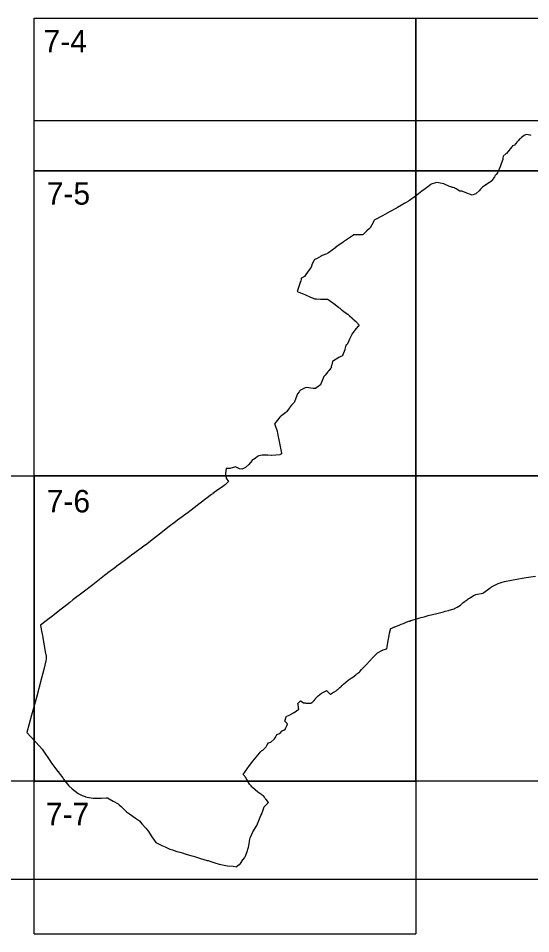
# Model space of a CAD drawing. Extents: x -449577 to -425530, y -1150048 to -1121091.
# Drawn here: x -436768.8 to -436559.1, y -1126653.4 to -1126278.4 of the extents above; entities that cross this region are included whole.
import ezdxf

# ---------------------------------------------------------------- set-up
doc = ezdxf.new("R2010")
doc.units = 0
for name, color, linetype in [('Vrstva 1', 7, 'Continuous'), ('Vrstva 10', 7, 'Continuous'), ('Vrstva 4', 7, 'Continuous')]:
    doc.layers.add(name, color=color, linetype=linetype)

msp = doc.modelspace()

# ---------------------------------------------------------------- linework, layer by layer
at = {"layer": 'Vrstva 1'}
for points in [[(-436558.93, -1126326.41), (-436559.39, -1126326.32), (-436560.98, -1126326), (-436561.28, -1126326.11), (-436561.84, -1126326.46), (-436562.39, -1126326.78), (-436562.88, -1126327.24), (-436563.41, -1126327.73), (-436563.81, -1126328.12), (-436563.82, -1126328.13), (-436564.15, -1126328.47), (-436564.28, -1126328.61), (-436564.79, -1126329.16), (-436565.24, -1126329.71), (-436565.4, -1126329.9), (-436565.76, -1126330.33), (-436566.5, -1126330.66), (-436566.52, -1126330.66), (-436566.72, -1126330.91), (-436567.58, -1126331.93), (-436567.96, -1126332.38), (-436569.09, -1126333.74), (-436569.1, -1126333.75), (-436570.34, -1126334.92), (-436570.46, -1126335.76), (-436570.51, -1126336.13), (-436570.55, -1126336.23), (-436571.03, -1126337.58), (-436571.47, -1126338.82), (-436571.5, -1126338.9), (-436571.8, -1126339.59), (-436572.73, -1126341.77), (-436572.75, -1126341.78), (-436573.32, -1126342.46), (-436573.62, -1126342.81), (-436573.62, -1126342.82), (-436573.96, -1126343.36), (-436574.83, -1126344.75), (-436574.92, -1126344.89), (-436575.09, -1126345.02), (-436575.62, -1126345.41), (-436576.23, -1126345.86), (-436576.23, -1126345.86), (-436577.2, -1126346.49), (-436577.33, -1126346.58), (-436577.51, -1126346.7), (-436578.81, -1126347.56), (-436578.82, -1126347.57), (-436579.08, -1126347.83), (-436579.2, -1126347.95), (-436579.42, -1126348.18), (-436579.7, -1126348.46), (-436580.27, -1126349.03), (-436581.43, -1126350.19), (-436581.63, -1126350.27), (-436583.13, -1126350.84), (-436585.94, -1126349.72), (-436585.94, -1126349.73), (-436585.95, -1126349.75), (-436586.86, -1126349.37), (-436587.17, -1126349.24), (-436587.19, -1126349.24), (-436587.58, -1126349.24), (-436588.06, -1126349.24), (-436589.62, -1126348.25), (-436589.88, -1126348.12), (-436590.17, -1126347.96), (-436590.23, -1126347.93), (-436590.27, -1126347.91), (-436590.81, -1126347.68), (-436590.86, -1126347.68), (-436590.87, -1126347.68), (-436591.02, -1126347.67), (-436591.14, -1126347.66), (-436591.45, -1126347.64), (-436591.47, -1126347.64), (-436591.47, -1126347.64), (-436591.58, -1126347.6), (-436591.82, -1126347.5), (-436592.42, -1126347.25), (-436592.58, -1126347.18), (-436594.1, -1126346.45), (-436594.72, -1126346.27), (-436595.39, -1126346.07), (-436597.71, -1126345.64), (-436597.72, -1126345.64), (-436598.12, -1126345.75), (-436599.86, -1126346.33), (-436599.99, -1126346.44), (-436601.2, -1126347.4), (-436601.2, -1126347.4), (-436602.35, -1126348.27), (-436602.92, -1126348.7), (-436603.5, -1126349.14), (-436603.66, -1126349.26), (-436605.79, -1126350.9), (-436606.86, -1126351.72), (-436607.33, -1126352.06), (-436608.09, -1126352.57), (-436608.34, -1126352.73), (-436608.93, -1126353.12), (-436608.97, -1126353.15), (-436609.18, -1126353.29), (-436610.09, -1126353.89), (-436610.1, -1126353.89), (-436610.57, -1126354.15), (-436610.72, -1126354.23), (-436610.9, -1126354.33), (-436611.36, -1126354.58), (-436611.54, -1126354.69), (-436611.7, -1126354.78), (-436611.8, -1126354.84), (-436612.04, -1126354.98), (-436613.7, -1126355.92), (-436613.87, -1126356.01), (-436614.1, -1126356.14), (-436616.57, -1126357.54), (-436616.69, -1126357.61), (-436618.8, -1126358.74), (-436619.82, -1126359.29), (-436623.16, -1126361.1), (-436623.33, -1126361.4), (-436623.39, -1126361.51), (-436624.17, -1126362.97), (-436624.85, -1126364.29), (-436624.99, -1126364.42), (-436625.08, -1126364.5), (-436626.22, -1126365.54), (-436627.73, -1126366.92), (-436627.9, -1126367.07), (-436627.9, -1126367.08), (-436628.37, -1126367.09), (-436631.56, -1126367.18), (-436631.57, -1126367.18), (-436632, -1126367.47), (-436632.83, -1126368.04), (-436635.3, -1126369.7), (-436635.34, -1126369.72), (-436635.58, -1126369.9), (-436635.85, -1126370.1), (-436638.83, -1126372.23), (-436638.9, -1126372.28), (-436641.9, -1126374.46), (-436642.37, -1126374.8), (-436642.53, -1126374.86), (-436644.47, -1126375.58), (-436644.48, -1126375.58), (-436644.87, -1126375.82), (-436646.75, -1126376.98), (-436647.67, -1126377.19), (-436647.92, -1126377.7), (-436648.68, -1126379.21), (-436648.69, -1126379.22), (-436648.76, -1126379.48), (-436648.96, -1126380.32), (-436649.79, -1126381.43), (-436651.16, -1126383.38), (-436651.72, -1126384.19), (-436651.75, -1126384.21), (-436652.91, -1126384.85), (-436653.01, -1126384.91), (-436653.08, -1126385.3), (-436653.23, -1126386.11), (-436653.28, -1126386.3), (-436654.57, -1126389.88), (-436654.74, -1126390.36), (-436654.71, -1126390.35), (-436654.69, -1126390.34), (-436654.01, -1126390.6), (-436652.2, -1126391.26), (-436651.58, -1126391.55), (-436649.29, -1126392.63), (-436649.27, -1126392.63), (-436648.11, -1126393.1), (-436647.64, -1126393.28), (-436647.61, -1126393.29), (-436647.18, -1126393.32), (-436647.04, -1126393.33), (-436646.82, -1126393.35), (-436645.22, -1126393.45), (-436644.18, -1126393.52), (-436643.13, -1126393.49), (-436642.29, -1126393.46), (-436642.28, -1126393.46), (-436642, -1126393.61), (-436641.63, -1126393.87), (-436641.08, -1126394.25), (-436640.69, -1126394.53), (-436639.13, -1126395.67), (-436638.96, -1126395.79), (-436637.85, -1126396.71), (-436637.46, -1126397.03), (-436637.28, -1126397.18), (-436636.53, -1126397.79), (-436636.26, -1126398.02), (-436635.66, -1126398.51), (-436635.44, -1126398.69), (-436634.8, -1126399.11), (-436634.05, -1126399.61), (-436634.02, -1126399.63), (-436633.26, -1126400.31), (-436632.38, -1126401.09), (-436631.94, -1126401.47), (-436630.93, -1126402.36), (-436630.67, -1126402.59), (-436630.62, -1126402.64), (-436630.52, -1126402.74), (-436630.51, -1126402.75), (-436630.42, -1126402.85), (-436630.39, -1126402.88), (-436629.34, -1126404.11), (-436629.35, -1126404.12), (-436629.79, -1126404.61), (-436629.85, -1126404.68), (-436630.42, -1126405.31), (-436631.24, -1126406.37), (-436631.41, -1126406.58), (-436631.97, -1126407.3), (-436632.27, -1126407.83), (-436632.29, -1126407.87), (-436632.3, -1126407.89), (-436632.43, -1126408.17), (-436633.23, -1126409.84), (-436633.54, -1126410.48), (-436634.16, -1126411.77), (-436634.27, -1126412.01), (-436634.28, -1126412.01), (-436634.32, -1126412.04), (-436634.61, -1126412.24), (-436634.69, -1126412.28), (-436634.74, -1126412.38), (-436634.83, -1126412.58), (-436634.92, -1126412.86), (-436635.09, -1126413.42), (-436635.1, -1126413.44), (-436635.22, -1126413.94), (-436635.24, -1126414.01), (-436635.23, -1126414.07), (-436635.22, -1126414.15), (-436635.22, -1126414.22), (-436635.23, -1126414.27), (-436636.11, -1126416.6), (-436636.13, -1126416.65), (-436636.15, -1126416.69), (-436636.16, -1126416.7), (-436636.86, -1126417), (-436637.11, -1126417.11), (-436637.58, -1126417.35), (-436640.19, -1126419.04), (-436640.19, -1126419.04), (-436640.56, -1126420.35), (-436640.64, -1126420.61), (-436640.75, -1126421.03), (-436640.81, -1126421.24), (-436640.81, -1126421.25), (-436640.8, -1126421.25), (-436640.63, -1126421.41), (-436640.64, -1126421.42), (-436641, -1126421.81), (-436641.8, -1126422.81), (-436641.81, -1126422.82), (-436642.02, -1126423.07), (-436642.02, -1126423.08), (-436642.14, -1126423.23), (-436643.3, -1126424.58), (-436643.84, -1126425.21), (-436644.6, -1126427.16), (-436644.98, -1126428.18), (-436645.11, -1126428.53), (-436646.64, -1126429.63), (-436647.26, -1126430.07), (-436647.44, -1126430.11), (-436647.46, -1126430.11), (-436648.09, -1126430.02), (-436650.93, -1126429.6), (-436651.42, -1126429.84), (-436652.75, -1126430.48), (-436653.29, -1126430.74), (-436653.32, -1126430.77), (-436653.75, -1126431.18), (-436653.92, -1126431.4), (-436654.58, -1126432.25), (-436654.58, -1126432.26), (-436655.25, -1126434.06), (-436655.82, -1126435.56), (-436655.82, -1126435.56), (-436655.96, -1126435.78), (-436656.29, -1126436.15), (-436657.01, -1126436.95), (-436657.71, -1126437.72), (-436657.72, -1126437.74), (-436657.85, -1126437.93), (-436658.92, -1126439.5), (-436659.39, -1126439.88), (-436660.96, -1126441.14), (-436661.63, -1126441.68), (-436661.73, -1126441.76), (-436661.76, -1126441.8), (-436662.88, -1126443.23), (-436664.02, -1126444.54), (-436663.87, -1126444.71), (-436663.86, -1126444.74), (-436663.86, -1126444.75), (-436662.85, -1126447.51), (-436662.57, -1126449.17), (-436662.25, -1126451.12), (-436661.84, -1126453.08), (-436661.11, -1126456.58), (-436661.07, -1126456.78), (-436661.72, -1126457.12), (-436661.84, -1126457.19), (-436665.01, -1126457.45), (-436665.17, -1126457.45), (-436666.66, -1126457.42), (-436669.05, -1126457.4), (-436670.33, -1126457.67), (-436670.93, -1126457.94), (-436671.91, -1126458.74), (-436673.21, -1126459.61), (-436673.3, -1126459.72), (-436674.46, -1126461.14), (-436675.91, -1126462.48), (-436676.6, -1126462.8), (-436677.2, -1126463.08), (-436678.37, -1126463.01), (-436679.98, -1126462.16), (-436682.22, -1126462.83), (-436683.7, -1126462.8), (-436684.08, -1126464.91), (-436684.09, -1126464.93), (-436684.1, -1126465.02), (-436683.81, -1126466.83), (-436682.84, -1126468.15), (-436682.83, -1126468.17), (-436683.57, -1126468.92), (-436684.18, -1126469.48), (-436684.43, -1126469.71), (-436685.23, -1126470.34), (-436687.16, -1126471.57), (-436687.22, -1126471.61), (-436689.19, -1126473.14), (-436689.25, -1126473.18), (-436689.74, -1126473.56), (-436694.4, -1126477.02), (-436694.43, -1126477.05), (-436699.38, -1126480.81), (-436703.64, -1126484.06), (-436704.52, -1126484.72), (-436707.09, -1126486.66), (-436711.09, -1126489.79), (-436713.53, -1126491.66), (-436716.84, -1126494.19), (-436716.89, -1126494.23), (-436721.68, -1126497.74), (-436721.91, -1126497.92), (-436725.52, -1126500.6), (-436727.91, -1126502.42), (-436729.88, -1126503.9), (-436732.2, -1126505.65), (-436732.43, -1126505.82), (-436733.56, -1126506.71), (-436738.38, -1126510.51), (-436742.27, -1126513.46), (-436746.49, -1126516.71), (-436747.78, -1126517.71), (-436750.17, -1126519.59), (-436751.35, -1126520.51), (-436755.29, -1126523.56), (-436756.22, -1126524.27), (-436757.46, -1126525.23), (-436759.78, -1126527.03), (-436759.78, -1126527.03), (-436759.74, -1126527.21), (-436759.45, -1126528.59), (-436759.42, -1126528.75), (-436758.89, -1126531.29), (-436758.73, -1126532.02), (-436758.73, -1126532.06), (-436757.8, -1126537.94), (-436757.79, -1126537.97), (-436757.49, -1126539.7), (-436757.49, -1126539.72), (-436757.43, -1126540.09), (-436757.37, -1126540.51), (-436757.4, -1126540.88), (-436757.55, -1126541.61), (-436757.93, -1126543.4), (-436758.22, -1126544.58), (-436758.24, -1126544.63), (-436759.35, -1126548.8), (-436761.45, -1126556.68), (-436763.44, -1126563.9), (-436765.37, -1126571), (-436765.38, -1126571.04), (-436760.1, -1126576.64), (-436759.05, -1126577.77), (-436758.29, -1126578.99), (-436756.27, -1126582.05), (-436756.22, -1126582.12), (-436755.21, -1126583.53), (-436755.05, -1126583.74), (-436753.17, -1126586.22), (-436752.6, -1126586.96), (-436752.57, -1126587), (-436752.05, -1126587.72), (-436750.67, -1126589.62), (-436750.34, -1126590.07), (-436748.19, -1126592.79), (-436746.79, -1126594.01), (-436744.39, -1126595.99), (-436742.65, -1126596.74), (-436741.46, -1126597.26), (-436741.33, -1126597.31), (-436740, -1126597.59), (-436739.86, -1126597.62), (-436738.24, -1126597.95), (-436738.21, -1126597.95), (-436737.25, -1126597.93), (-436736.87, -1126597.93), (-436736.35, -1126597.92), (-436735.67, -1126597.91), (-436734.76, -1126597.87), (-436732.81, -1126597.71), (-436732.36, -1126597.78), (-436731.7, -1126598.13), (-436729.98, -1126599.08), (-436728.02, -1126600.18), (-436727.5, -1126600.66), (-436726.78, -1126601.34), (-436725.98, -1126602.09), (-436724.66, -1126603.39), (-436724.52, -1126603.49), (-436723.33, -1126604.34), (-436720.92, -1126606.05), (-436719.28, -1126607.23), (-436718.23, -1126608.41), (-436716.59, -1126610.23), (-436715.95, -1126610.94), (-436715.59, -1126611.53), (-436715.13, -1126612.27), (-436714.19, -1126613.74), (-436713.56, -1126614.66), (-436712.52, -1126616.1), (-436711.45, -1126616.61), (-436710.07, -1126617.26), (-436708.76, -1126617.87), (-436706.79, -1126618.76), (-436705.66, -1126619.11), (-436703.94, -1126619.68), (-436703.79, -1126619.73), (-436702.7, -1126620.05), (-436701.28, -1126620.47), (-436701.27, -1126620.47), (-436701.06, -1126620.53), (-436701, -1126620.55), (-436700.14, -1126620.81), (-436697.75, -1126621.5), (-436697.63, -1126621.54), (-436697.15, -1126621.68), (-436694.22, -1126622.55), (-436691.53, -1126623.38), (-436691.19, -1126623.48), (-436690.43, -1126623.71), (-436688.42, -1126624.33), (-436686.69, -1126624.88), (-436683.23, -1126625.62)], [(-436683.23, -1126625.62), (-436680.84, -1126625.81), (-436679.64, -1126626.04), (-436679.53, -1126625.95), (-436677.95, -1126624.68), (-436676.92, -1126623.2), (-436676.81, -1126623.05), (-436676.29, -1126622.29), (-436676.18, -1126622.12), (-436676.04, -1126621.89), (-436675.66, -1126621.26), (-436675.39, -1126620.43), (-436675.37, -1126620.36), (-436675.35, -1126620.31), (-436675.32, -1126620.2), (-436675.29, -1126620.11), (-436675.29, -1126620.1), (-436674.66, -1126617.9), (-436674.52, -1126617.38), (-436674.07, -1126614.63), (-436674.07, -1126614.63), (-436673.88, -1126614.19), (-436673.62, -1126613.57), (-436672.83, -1126611.74), (-436671.26, -1126609.09), (-436669.51, -1126604.96), (-436669.19, -1126604.32), (-436669.15, -1126604.19), (-436668.76, -1126603.09), (-436668.17, -1126601.42), (-436666.49, -1126599.71), (-436667.42, -1126598.47), (-436667.48, -1126598.38), (-436667.53, -1126598.32), (-436667.56, -1126598.28), (-436667.63, -1126598.18), (-436667.68, -1126598.1), (-436667.76, -1126597.98), (-436668.12, -1126597.46), (-436668.49, -1126597), (-436669.06, -1126596.63), (-436669.16, -1126596.57), (-436670.81, -1126595.5), (-436673, -1126593.56), (-436673.13, -1126593.39), (-436673.16, -1126593.35), (-436673.24, -1126593.25), (-436673.58, -1126592.83), (-436673.91, -1126592.42), (-436674.17, -1126592.1), (-436674.65, -1126591.51), (-436674.73, -1126591.41), (-436675.23, -1126590.45), (-436675.52, -1126589.89), (-436675.75, -1126589.46), (-436675.8, -1126589.37), (-436675.84, -1126589.32), (-436676.1, -1126589.03), (-436676.3, -1126588.8), (-436676.56, -1126588.51), (-436676.78, -1126588.26), (-436674.92, -1126585.52), (-436674.83, -1126585.4), (-436674.51, -1126584.95), (-436674.19, -1126584.51), (-436672.86, -1126582.68), (-436670.18, -1126579.42), (-436669.83, -1126579.1), (-436669.12, -1126578.4), (-436669.01, -1126578.31), (-436668.82, -1126578.17), (-436668.22, -1126577.69), (-436667.36, -1126576.85), (-436666.95, -1126576.09), (-436666.48, -1126575.22), (-436665.43, -1126574.98), (-436664.03, -1126573.55), (-436663.49, -1126572.7), (-436663.48, -1126572.69), (-436663.48, -1126572.67), (-436663.27, -1126572.34), (-436663.22, -1126572.26), (-436662.98, -1126571.87), (-436661.82, -1126571.43), (-436660.8, -1126570.25), (-436660.27, -1126570.05), (-436660.15, -1126570), (-436659.73, -1126569.84), (-436659.51, -1126569.45), (-436659.46, -1126569.36), (-436659.29, -1126569.06), (-436658.88, -1126568.32), (-436658.68, -1126567.41), (-436658.68, -1126567.39), (-436658.67, -1126567.38), (-436659.72, -1126566.39), (-436659.74, -1126566.38), (-436659.75, -1126566.36), (-436659.8, -1126566.32), (-436659.15, -1126564.52), (-436659.08, -1126564.32), (-436658.92, -1126564.26), (-436658.19, -1126563.97), (-436657.5, -1126563.7), (-436657.38, -1126563.65), (-436656.17, -1126562.94), (-436656.05, -1126562.86), (-436656.05, -1126562.86), (-436656.04, -1126562.85), (-436655.92, -1126562.78), (-436654.06, -1126561.38), (-436654.06, -1126561.34), (-436654.09, -1126561.18), (-436654.16, -1126560.7), (-436654.22, -1126560.35), (-436654.32, -1126559.73), (-436654.34, -1126559.62), (-436654.36, -1126559.49), (-436654.38, -1126559.32), (-436654.41, -1126559.18), (-436653.87, -1126558.62), (-436653.31, -1126558.05), (-436653.27, -1126558), (-436653.13, -1126558.1), (-436652.13, -1126558.89), (-436651.45, -1126558.9), (-436651.39, -1126558.9), (-436651.14, -1126558.91), (-436650.98, -1126558.91), (-436649.67, -1126558.93), (-436649.04, -1126558.95), (-436648.77, -1126558.79), (-436648.74, -1126558.77), (-436648.62, -1126558.7), (-436648.48, -1126558.61), (-436648.44, -1126558.58), (-436647.9, -1126557.98), (-436647.79, -1126557.86), (-436647.7, -1126557.76), (-436647.53, -1126557.58), (-436647.45, -1126557.49), (-436647.34, -1126557.37), (-436647.31, -1126557.33), (-436647.28, -1126557.3), (-436647.23, -1126557.24), (-436647.14, -1126557.13), (-436646.74, -1126556.63), (-436646.53, -1126556.37), (-436646.28, -1126556.05), (-436646.17, -1126555.97), (-436644.71, -1126554.9), (-436644.5, -1126554.77), (-436643.14, -1126554), (-436642.74, -1126553.77), (-436642.74, -1126553.77), (-436642.6, -1126553.92), (-436641.89, -1126554.63), (-436641.52, -1126555.01), (-436641.34, -1126555.18), (-436641.19, -1126555.33), (-436641.1, -1126555.29), (-436639.82, -1126554.52), (-436639.73, -1126554.47), (-436638.8, -1126553.91), (-436638.76, -1126553.88), (-436638.43, -1126553.59), (-436638.38, -1126553.55), (-436638.21, -1126553.4), (-436638.2, -1126553.39), (-436638.2, -1126553.39), (-436638.16, -1126553.35), (-436638.12, -1126553.31), (-436637.23, -1126552.5), (-436637.21, -1126552.49), (-436636.62, -1126551.95), (-436636.51, -1126551.86), (-436636.4, -1126551.76), (-436636.4, -1126551.76), (-436636.39, -1126551.76), (-436636.39, -1126551.76), (-436636.39, -1126551.75), (-436636.38, -1126551.75), (-436636.37, -1126551.74), (-436636.37, -1126551.74), (-436636.36, -1126551.73), (-436636.36, -1126551.73), (-436636.35, -1126551.73), (-436636.35, -1126551.73), (-436635.77, -1126551.24), (-436633.78, -1126549.56), (-436632.58, -1126548.71), (-436632.46, -1126548.63), (-436632.41, -1126548.59), (-436632.39, -1126548.58), (-436632.34, -1126548.55), (-436631.98, -1126548.28), (-436630.74, -1126547.34), (-436630.56, -1126547.2), (-436630.35, -1126547.04), (-436630.33, -1126547.02), (-436629.45, -1126546.35), (-436629.1, -1126546.08), (-436629.05, -1126546.02), (-436628.96, -1126545.92), (-436628.32, -1126545.24), (-436627.42, -1126544.26), (-436626.06, -1126542.85), (-436625.84, -1126542.62), (-436625.59, -1126542.34), (-436624.75, -1126541.39), (-436624.46, -1126541.07), (-436624.26, -1126540.86), (-436623.97, -1126540.54), (-436622.79, -1126539.35), (-436621.86, -1126538.33), (-436619.8, -1126537.32), (-436619.64, -1126537.27), (-436619.44, -1126537.19), (-436618, -1126536.7), (-436617.85, -1126535.83), (-436617.69, -1126534.96), (-436617.27, -1126532.59), (-436617.19, -1126532.12), (-436616.86, -1126530.24), (-436616.66, -1126529.36), (-436616.63, -1126529.24), (-436616.58, -1126529.05), (-436616.57, -1126529.01), (-436616.55, -1126528.94), (-436616.54, -1126528.9), (-436616.53, -1126528.85), (-436616.52, -1126528.81), (-436616.51, -1126528.79), (-436616.45, -1126528.58), (-436615.37, -1126528.04), (-436615.08, -1126527.9), (-436615.06, -1126527.89), (-436614.81, -1126527.76), (-436614.76, -1126527.74), (-436612.99, -1126527.02), (-436612.96, -1126527.01), (-436612.93, -1126526.99), (-436612.13, -1126526.68), (-436611.17, -1126526.28), (-436610.36, -1126525.94), (-436609.42, -1126525.55), (-436609.34, -1126525.52), (-436608.73, -1126525.28), (-436608.88, -1126525.44), (-436608.64, -1126525.35), (-436608.15, -1126525.15), (-436607.62, -1126524.99), (-436605.92, -1126524.47), (-436605.33, -1126524.3), (-436604.88, -1126524.18), (-436603.99, -1126523.93), (-436602.68, -1126523.55), (-436601.14, -1126523.09), (-436597.6, -1126522.22), (-436594.83, -1126521.55), (-436594.16, -1126521.34), (-436592.67, -1126520.98), (-436592.46, -1126520.92), (-436591.03, -1126520.53), (-436590.43, -1126520.27), (-436590.21, -1126520.17), (-436590.05, -1126520.11), (-436589.23, -1126519.66), (-436589.17, -1126519.62), (-436587.86, -1126518.84), (-436586.71, -1126517.79), (-436586.06, -1126517.29), (-436585.93, -1126517.18), (-436585.91, -1126517.17), (-436585.75, -1126517.04), (-436585.6, -1126516.94), (-436584.8, -1126516.38), (-436584.74, -1126516.34), (-436584.67, -1126516.29), (-436584.16, -1126515.94), (-436583.79, -1126515.68), (-436583.13, -1126515.22), (-436582.54, -1126514.81), (-436582.38, -1126514.84), (-436582.37, -1126514.84), (-436582.35, -1126514.82), (-436581.62, -1126514.43), (-436578.66, -1126513.85), (-436578.24, -1126513.7), (-436576.21, -1126512.07), (-436575.74, -1126511.73), (-436575.71, -1126511.71), (-436575.35, -1126511.45), (-436575.17, -1126511.33), (-436573.78, -1126510.63), (-436572.37, -1126509.99), (-436572.07, -1126509.84), (-436570.81, -1126509.38), (-436569.81, -1126509.13), (-436564.1, -1126508.07), (-436562.68, -1126507.81), (-436560.97, -1126507.56), (-436557.1, -1126506.99)]]:
    msp.add_lwpolyline(points, dxfattribs=at)
at = {"layer": 'Vrstva 10'}
msp.add_lwpolyline([(-436449.84, -1126320.23), (-436449.84, -1126631.21), (-436782.71, -1126631.21), (-436782.71, -1126465.91), (-436762.34, -1126465.91), (-436762.34, -1126340.91), (-436762.34, -1126320.23), (-436449.84, -1126320.23)], dxfattribs=at)
at = {"layer": 'Vrstva 4'}
for p, q in [((-436762.34, -1126278.41), (-436449.84, -1126278.41)), ((-436762.34, -1126653.41), (-436606.09, -1126653.41))]:
    msp.add_line(p, q, dxfattribs=at)
for points in [[(-436606.09, -1126278.41), (-436606.09, -1126340.91), (-436762.34, -1126340.91), (-436762.34, -1126278.41)], [(-436449.84, -1126278.41), (-436449.84, -1126340.91), (-436606.09, -1126340.91), (-436606.09, -1126278.41)], [(-436840.47, -1126465.91), (-436762.34, -1126465.91), (-436762.34, -1126590.91), (-436840.47, -1126590.91)], [(-436762.34, -1126653.41), (-436762.34, -1126590.91), (-436606.09, -1126590.91), (-436606.09, -1126653.41)]]:
    msp.add_lwpolyline(points, dxfattribs=at)
for points in [[(-436606.09, -1126340.91), (-436606.09, -1126465.91), (-436762.34, -1126465.91), (-436762.34, -1126340.91)], [(-436449.84, -1126340.91), (-436449.84, -1126465.91), (-436606.09, -1126465.91), (-436606.09, -1126340.91)], [(-436606.09, -1126465.91), (-436606.09, -1126590.91), (-436762.34, -1126590.91), (-436762.34, -1126465.91)], [(-436449.84, -1126465.91), (-436449.84, -1126590.91), (-436606.09, -1126590.91), (-436606.09, -1126465.91)]]:
    msp.add_lwpolyline(points, close=True, dxfattribs=at)

# ---------------------------------------------------------------- texts
at = {"layer": 'Vrstva 1'}
for s, p in [('7-4', (-436758.53, -1126292.41)), ('7-5', (-436757.22, -1126354.75)), ('7-6', (-436757.22, -1126480.82)), ('7-7', (-436757.58, -1126608.99))]:
    msp.add_text(s, height=9.2, dxfattribs=at).set_placement(p)

doc.saveas('drawing.dxf')
